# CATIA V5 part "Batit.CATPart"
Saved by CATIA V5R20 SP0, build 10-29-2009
Part number: Batit
Bounding box of the stored display mesh (mm): x 0 to 20, y 0 to 38.491, z -63 to 0
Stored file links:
  C:\Users\ASUS\Desktop\Think Motion IAO\Batit.CATPart
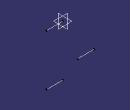
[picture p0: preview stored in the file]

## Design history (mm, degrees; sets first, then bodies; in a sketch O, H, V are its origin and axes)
Body1 (main body)
  Point1 "Point.A": stored without definition
  Line1: type PtDir, RefPoint Point1, Direction yz-plane, Start 0, End 20
  Point2 "Point.C": stored without definition
  Line2: type PtDir, RefPoint Point2, Direction yz-plane, Start 0, End 20
  Point3 "Point.G": stored without definition
  Line3: type PtDir, RefPoint Point3, Direction yz-plane, Start 0, End 20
